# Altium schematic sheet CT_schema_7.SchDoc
size 366 x 333 mm
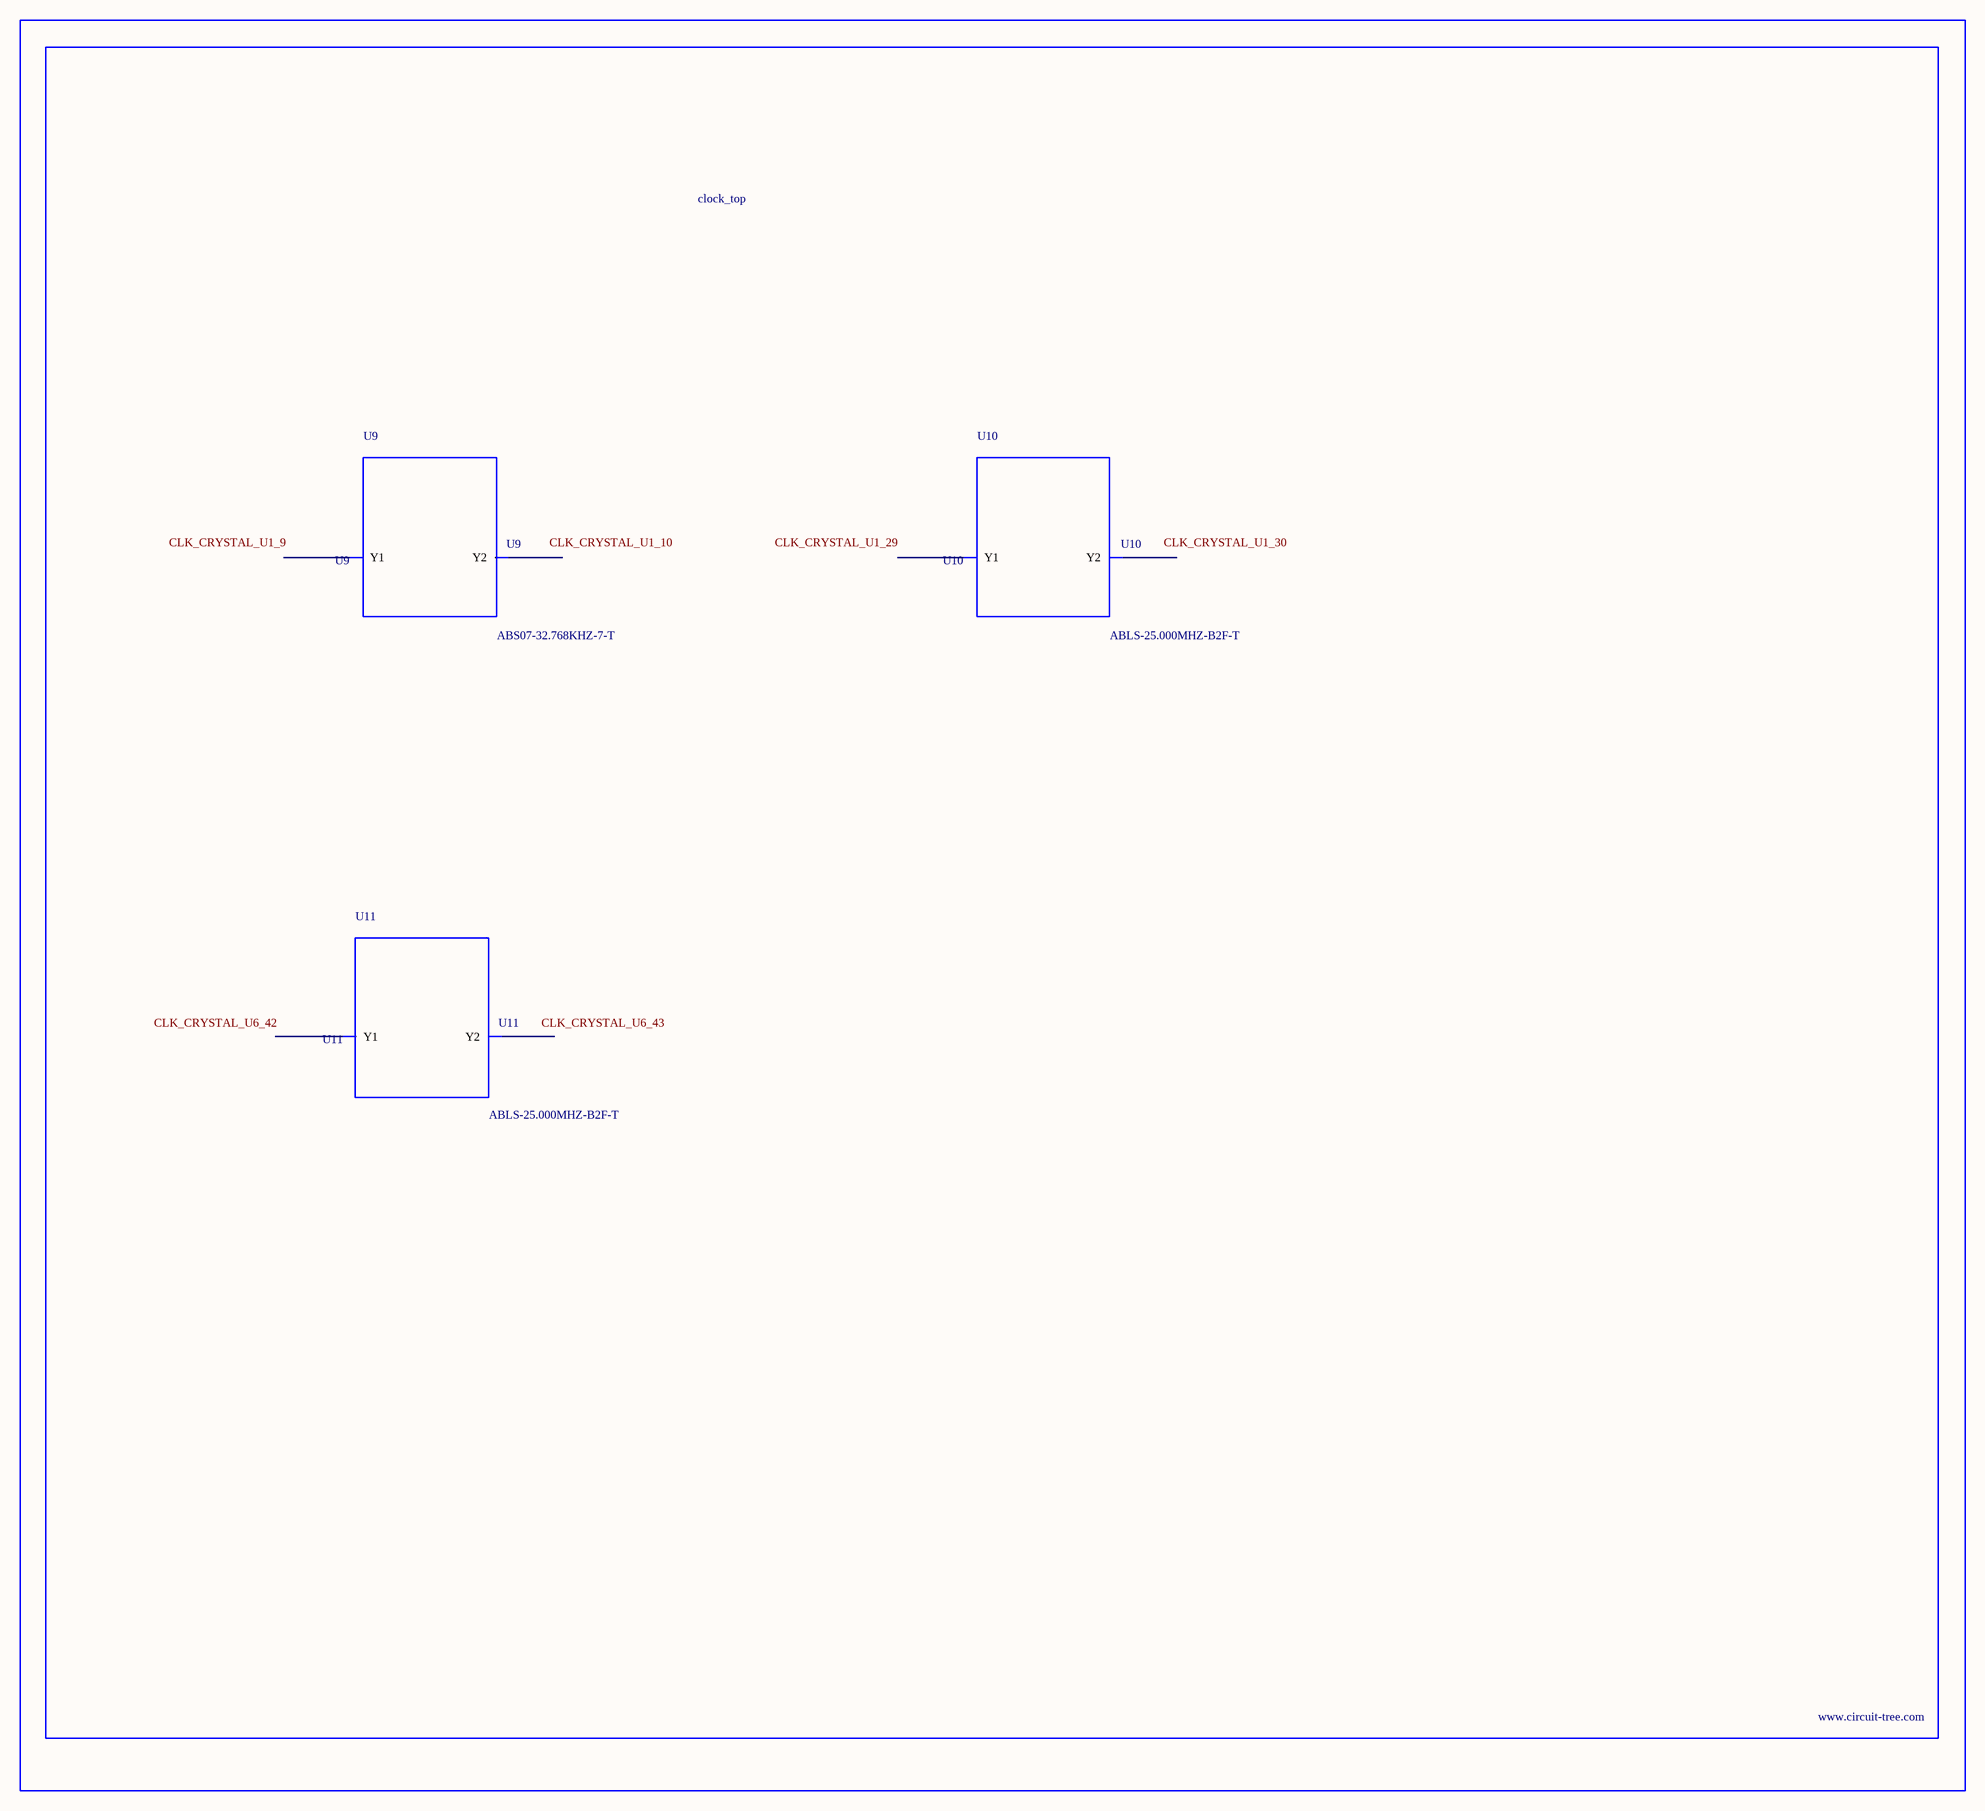
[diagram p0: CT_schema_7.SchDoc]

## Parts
BORDER6  (no value)
U9  ABS07-32.768KHZ-7-T  [ABS07-32.768KHZ-7-T]
U10  ABLS-25.000MHZ-B2F-T  [ABLS-25.000MHZ-B2F-T]
U11  ABLS-25.000MHZ-B2F-T  [ABLS-25.000MHZ-B2F-T]

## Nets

Not connected (* = marked no-connect by the designer): U9 1(Y1) 2(Y2); U10 1(Y1) 2(Y2); U11 1(Y1) 2(Y2)

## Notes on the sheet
- Labels drawn without touching a wire or pin: CLK_CRYSTAL_U1_9, CLK_CRYSTAL_U1_10, CLK_CRYSTAL_U1_29, CLK_CRYSTAL_U1_30, CLK_CRYSTAL_U6_42, CLK_CRYSTAL_U6_43

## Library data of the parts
BORDER6 = BORDER_PAGE6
